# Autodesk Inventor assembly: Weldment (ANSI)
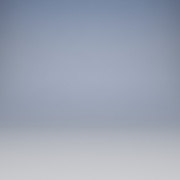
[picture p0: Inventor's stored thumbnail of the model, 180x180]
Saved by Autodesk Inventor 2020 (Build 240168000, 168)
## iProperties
Length Units: 11272
Angle Units: 11286
Time Units: 11279
Mass Units: 11290
Length Display Precision: 3
Angle Display Precision: 2
Part Number: Weldment (ANSI)
Document SubType Name: Weldment
Created: 2002-06
Designer: smithga
Created: 2002-08
Designer: F.Stasiak
Weld Material: Welded Aluminum-6061
Catalog Web Link: www.expertbooks.pl
Manager: www.cadconsulting.pl
Company: Fabian Stasiak CAD Consulting
Control State: 0
Master: False
Shininess: 64.0
Angle Units: 11279
Time Units: 11290
Mass Units: 11286
Compacted: True
Density: 0.0
Volumn: 0.0
Area: 0.0
PropertySet Name: Model Information
Author: F.Stasiak
Subject: Zbiór ćwiczeń. Autodesk Inventor 2020. Kurs Professional
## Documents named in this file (1)
- M:\AUTOBUILD\M24_168_RTM\Application\App\Templates\en-US\English\Weldment (ANSI).iam
